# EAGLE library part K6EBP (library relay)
RELAY Socked NAiS Source: http://www.mew-europe.com/.. en_ds_61013_0000.pdf
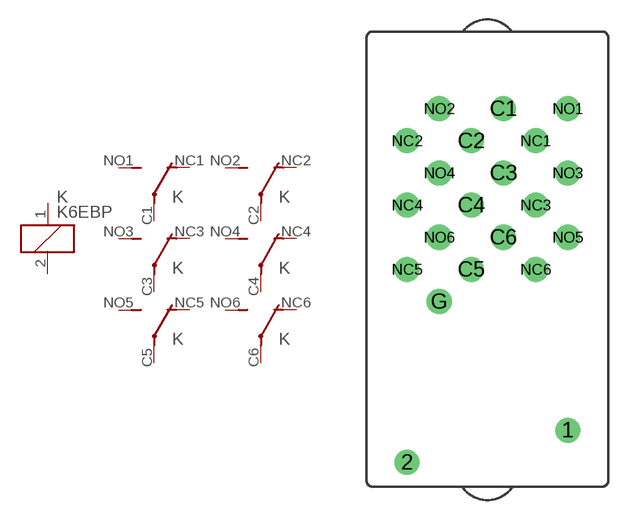
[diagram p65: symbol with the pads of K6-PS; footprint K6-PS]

Designator prefix K; gates _=K 1=U 2=U 3=U 4=U 5=U 6=U

## K6EBPS (OC_FARNELL: unknown; OC_NEWARK: unknown)  [K6-PS]
1  _:1  pas
2  _:2  pas
C1  1:P  pas
C2  2:P  pas
C3  3:P  pas
C4  4:P  pas
C5  5:P  pas
C6  6:P  pas
NC1  1:O  pas
NC2  2:O  pas
NC3  3:O  pas
NC4  4:O  pas
NC5  5:O  pas
NC6  6:O  pas
NO1  1:S  pas
NO2  2:S  pas
NO3  3:S  pas
NO4  4:S  pas
NO5  5:S  pas
NO6  6:S  pas

## Footprint K6-PS (pad centres in mm)
RELAY Socked NAiS Source: http://www.mew-europe.com/.. en_ds_61013_0000.pdf
drill 1.3 round: 1 6.25,-6.25; 2 -6.25,-8.75; C1 1.25,18.75; C2 -1.25,16.25; C3 1.25,13.75; C4 -1.25,11.25; C5 -1.25,6.25; C6 1.25,8.75; G -3.75,3.75; NC1 3.75,16.25; NC2 -6.25,16.25; NC3 3.75,11.25; NC4 -6.25,11.25; NC5 -6.25,6.25; NC6 3.75,6.25; NO1 6.25,18.75; NO2 -3.75,18.75; NO3 6.25,13.75; NO4 -3.75,13.75; NO5 6.25,8.75; NO6 -3.75,8.75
